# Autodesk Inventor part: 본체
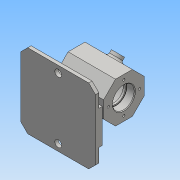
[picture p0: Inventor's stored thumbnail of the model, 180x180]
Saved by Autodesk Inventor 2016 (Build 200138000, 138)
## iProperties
Created: 2018-06
Part Number: 본체
Material: Generic
Document SubType Name: Modeling
Designer: MIRAE
Density: 1 g/cm^3
Appearance: Default
Author: MIRAE
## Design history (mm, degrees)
sketch "스케치1"
  geometry: L1 (-55, -55)-(55, -55); L2 (55, -55)-(55, 55); L3 (55, 55)-(-55, 55); L4 (-55, 55)-(-55, -55); L5 (-55, -55)-(55, 55); L6 (55, -55)-(-55, 55); 1 further point
  constraints: 12 end point, 2 midpoint, 2 parallel, 1 horizontal, 1 perpendicular
  dimensions: "d0" = 110 distance of L3.end L2.end; "d1" = 110 distance of L2.end L1.end
extrude "돌출1" new body sketch "스케치1" distance "d2" = 10; taper "d3" = 0 deg
sketch "스케치2"
  geometry: L1 (0, 10)-(30, 10); L2 (30, 10)-(30, 5); L3 (30, 5)-(0, 5); L4 (0, 5)-(0, 10); L5 (0, 10)-(110, 10) reference; L6 (110, 10)-(80, 10); L7 (80, 10)-(80, 5); L8 (80, 5)-(110, 5); L9 (110, 5)-(110, 10); 1 further point
  constraints: 16 end point, 4 parallel, 2 horizontal, 2 perpendicular
  dimensions: "d4" = 30 distance of L2.end L3.end; "d5" = 5 distance of L1.end L2.end; "d6" = 30 distance of L8.end L7.end; "d7" = 5 distance between parallel lines of L5 L8
extrude "돌출2" cut sketch "스케치2" stored distance "d8" = 10; taper "d9" = 0 deg
chamfer "모따기1" distance "d10" = 10; stored, may be unused: second distance "d11" = 2, angle "d12" = 45 deg
sketch "스케치3" dims "d15" = 60
  geometry: L1 (0, 0)-(62, 0); L2 (92, -12.426)-(74.426, -30); L3 (74.426, -30)-(49.574, -30); L4 (49.574, -30)-(32, -12.426); L5 (32, -12.426)-(32, 12.426); L6 (32, 12.426)-(49.574, 30); L7 (49.574, 30)-(74.426, 30); L8 (74.426, 30)-(92, 12.426); L9 (92, 12.426)-(92, -12.426); 5 further points
  constraints: 18 end point, 4 coincident, 1 horizontal, 1 horizontal alignment, 1 midpoint, 1 point on line, 19 other
  dimensions: "d13" = 62 distance of L1.start L1.end
extrude "돌출3" join sketch "스케치3" distance "d16" = 35; taper "d17" = 0 deg
sketch "스케치4"
  geometry: L1 (-45, 0)-(45, 0) reference; C1 r 25 at (0, 62); 2 further points
  constraints: 1 centre point, 1 midpoint, 1 vertical alignment
  dimensions: "d18" = 50 diameter of C1; "d19" = 62 distance from line of L1 C1.centre
extrude "돌출4" cut sketch "스케치4" distance "d20" = 20; taper "d21" = 0 deg
sketch "스케치5"
  geometry: L1 (-45, -62)-(45, -62) reference; C1 r 14 at (0, 0); 2 further points
  constraints: 1 centre point, 1 midpoint, 1 vertical alignment
  dimensions: "d23" = 28 diameter of C1; "d24" = 62 distance from line of L1 C1.centre
extrude "돌출5" cut sketch "스케치5" distance "d25" = 3; taper "d26" = 0 deg
sketch "스케치6"
  geometry: L1 (-45, -62)-(45, -62) reference; C1 r 16 at (0, 0); 2 further points
  constraints: 1 centre point, 1 midpoint, 1 vertical alignment
  dimensions: "d27" = 32 diameter of C1; "d28" = 62 distance from line of L1 C1.centre
extrude "돌출6" cut sketch "스케치6" stored distance "d29" = 3; taper "d30" = 0 deg
fillet "모깎기1" dims "d31" = 0.3, "d32" = 3
sketch "스케치7" dims "d33" = 46
  geometry: C1 r 16 at (0, 62) reference; 3 further points
  constraints: 1 coincident, 1 vertical alignment, 2 other
hole "구멍1" sketch "스케치7" at (0, 85) diameter "d34" = 3.242; stored, may be unused: countersink angle "d38" = 90 deg, drill point angle "d40" = 118 deg; dims "d35" = 8, "d36" = 4, "d37" = 2, "d39" = 10
chamfer "모따기2" distance "d44" = 1; stored, may be unused: second distance "d45" = 2, angle "d46" = 45 deg
sketch "스케치8"
  geometry: L1 (19, -5)-(-19, -5); L2 (19, 5)-(-19, 5); A1 r 5 centre (19, 0) between (19, -5) and (19, 5); A2 r 5 centre (-19, 0) between (-19, 5) and (-19, -5); 1 further point
  constraints: 4 end point, 4 point on circle, 3 tangent, 2 centre point, 2 horizontal alignment, 1 horizontal
  dimensions: "d47" = 10 diameter of A1; "d48" = 10 diameter of A2; "d49" = 38 distance of A2.centre A1.centre; "d50" = 19 distance of point (0, 0) A2.centre
extrude "돌출7" join sketch "스케치8" stored distance "d51" = 3; taper "d52" = 0 deg
sketch "스케치9"
  geometry: L1 (10, 30)-(100, 30) reference; C1 r 5 at (55, 20); 2 further points
  constraints: 1 centre point, 1 midpoint, 1 vertical alignment
  dimensions: "d53" = 10 diameter of C1; "d54" = 10 distance from line of L1 C1.centre
extrude "돌출8" cut sketch "스케치9" stored distance "d55" = 3; taper "d56" = 0 deg
node "작업 평면1"
sketch "스케치11"
  geometry: L1 (-58.417, 17.372)-(-11.292, 17.372); L2 (-11.292, 17.372)-(-11.292, 6.318); L3 (-11.292, 6.318)-(-58.417, 6.318); L4 (-58.417, 6.318)-(-58.417, 17.372); L5 (-70, 24.853)-(0, 24.853) reference; L6 (-70, 24.853)-(-70, 0) reference; L7 (0, 42.426)-(-70, 42.426) reference; 3 further points
  constraints: 2 midpoint, 1 horizontal alignment, 1 vertical alignment, 2 other
feature "엠보싱1" sketch "스케치11" dims "d0" = 110, "d1" = 110, "d58" = 0.5, "d59" = 0
node "작업 평면2"
sketch "스케치12"
  geometry: L1 (0, 24.853)-(0, 0) reference; L2 (70, 24.853)-(0, 24.853) reference; L3 (0, 42.426)-(70, 42.426) reference; C1 r 8 at (35, 12.426); 1 further point
  constraints: 1 centre point
  dimensions: "d61" = 16 diameter of C1; "d62" = 35 distance from line of L1 C1.centre; "d64" = 30 distance from line of L3 C1.centre
extrude "돌출9" join sketch "스케치12" stored distance "d65" = 3; taper "d66" = 0 deg
sketch "스케치13"
  geometry: C1 r 8 at (0, 0) reference; C2 r 4 at (0, 0); 1 further point
  constraints: 1 centre point, 1 coincident
  dimensions: "d67" = 8 diameter of C2
extrude "돌출10" cut sketch "스케치13" stored distance "d68" = 3; taper "d69" = 0 deg
fillet "모깎기2" dims "d70" = 3, "d71" = 2
chamfer "모따기3" distance "d72" = 1; stored, may be unused: second distance "d73" = 2, angle "d74" = 45 deg
node "솔리드1"
pattern_circular "원형 패턴1" dims angle "d42" = 360 deg
mirror "대칭1"
mirror "대칭2"
other parameters: "d57" = 27, "d60" = 7
